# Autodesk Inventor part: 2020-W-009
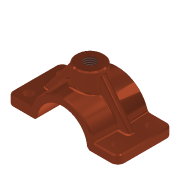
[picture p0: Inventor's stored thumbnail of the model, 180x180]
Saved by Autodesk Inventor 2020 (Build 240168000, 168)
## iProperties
Created: 2013-12
Part Number: 2020-W-009
Material: Miedź
Document SubType Name: Modeling
Designer: F.Stasiak
Density: 8.94 g/cm^3
Appearance: Miedź — satynowa
Manager: www.cadconsulting.pl
Company: Fabian Stasiak CAD Consulting
Author: F.Stasiak
Subject: Zbiór ćwiczeń. Autodesk Inventor 2020. Kurs podstawowy
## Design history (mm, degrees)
sketch "Szkic1"
  geometry: L1 (-50, 7.5)-(-29.047, 7.5); L2 (29.047, 7.5)-(50, 7.5); L3 (-50, 7.5)-(-50, 0); L4 (50, 0)-(50, 7.5); L5 (-50, 0)-(50, 0); L6 (-38.775, 7.5)-(-10, 45); L7 (-10, 45)-(10, 45); L8 (10, 45)-(38.775, 7.5); A1 r 30 centre (0, 0) between (29.047, 7.5) and (-29.047, 7.5); 3 further points
  constraints: 16 end point, 2 coincident, 2 collinear, 2 equal length, 2 midpoint, 2 parallel, 2 point on circle, 2 point on line, 1 centre point, 1 perpendicular, 1 vertical, 1 vertical alignment
  dimensions: "d1" = 100 distance of L4.start L3.end; "d3" = 7.5 distance between parallel lines of L2 L5; "d4" = 30 radius of A1; "d5" = 45 distance between parallel lines of L7 L5; "d6" = 20 distance of L6.end L7.end; "d7" = 75 deg angle of L8 L6
extrude "Wyciągnięcie proste1" new body sketch "Szkic1" stored distance "d8" = 50; taper "d9" = 0 deg
extrude "Wyciągnięcie proste2" join sketch "Szkic1" stored distance "d10" = 6; taper "d11" = 0 deg
feature "Pochylenie ściany1" dims angle "d12" = 2.5 deg
feature "Pochylenie ściany2" dims angle "d13" = 2.5 deg
sketch "Szkic2"
  geometry: C1 r 12.5 at (10, 3); 1 further point
  constraints: 1 centre point, 1 coincident
  dimensions: "d14" = 25 diameter of C1
extrude "Wyciągnięcie proste3" join sketch "Szkic2" distance "d15" = 20; taper "d17" = 2.5 deg; dims "d16" = 5, "d18" = -2.5 deg
sketch "Szkic3"
  geometry: C1 r 22.5 at (0, 0); A1 r 29.039 centre (0, 0) between (28.054, 7.5) and (-28.054, 7.5) reference
  constraints: 1 centre point, 1 coincident
  dimensions: "d19" = 45 diameter of C1
extrude "Wyciągnięcie proste4" cut sketch "Szkic3" extent not by distance; stored distance "d20" = 20; taper "d21" = 0 deg
sketch "Szkic4"
  geometry: L1 (0, 50)-(21.946, 50) reference; L2 (0, 50)-(0, 0) reference; L3 (88.775, 22)-(79.047, 22) reference; L4 (100, 0)-(78.054, 0) reference; L5 (100, 50)-(100, 0) reference; L6 (78.054, 50)-(100, 50) reference; L7 (79.047, 28)-(88.775, 28) reference; L8 (88.775, 28)-(88.775, 22) reference; L9 (90, 40)-(10, 40); L10 (10, 40)-(10, 10); L11 (10, 10)-(90, 10); L12 (90, 10)-(90, 40); L13 (90, 40)-(10, 10); L14 (10, 40)-(90, 10); 1 further point
  constraints: 12 end point, 2 midpoint, 2 parallel, 1 horizontal, 1 perpendicular, 2 other
  dimensions: "d22" = 10 distance between parallel lines of L2 L10; "d23" = 10 distance between parallel lines of L1 L9 (= d22)
hole "Otwór1" sketch "Szkic4" at (10, 40), (10, 10), (90, 10), (90, 40) diameter "d24" = 8; stored, may be unused: countersink angle "d28" = 90 deg, drill point angle "d30" = 118 deg; dims "d25" = 6, "d26" = 4, "d27" = 2, "d29" = 8
hole "Otwór2" diameter "d33" = 10.106; stored, may be unused: countersink angle "d37" = 90 deg, drill point angle "d39" = 118 deg; dims "d34" = 6, "d35" = 4, "d36" = 2, "d38" = 8, "d53" = 10, "d54" = 10
fillet "Zaokrąglenie1" dims "d40" = 6
fillet "Zaokrąglenie2" dims "d41" = 2
fillet "Zaokrąglenie3" dims "d42" = 2
fillet "Zaokrąglenie4" dims "d43" = 2
chamfer "Faza1" distance "d44" = 2; stored, may be unused: second distance "d45" = 2, angle "d46" = 45 deg
chamfer "Faza2" distance "d47" = 1; stored, may be unused: second distance "d48" = 2, angle "d49" = 45 deg
chamfer "Faza3" distance "d50" = 1; stored, may be unused: second distance "d51" = 2, angle "d52" = 45 deg
node "Bryła1"
node "Pętla rzutowana1"
